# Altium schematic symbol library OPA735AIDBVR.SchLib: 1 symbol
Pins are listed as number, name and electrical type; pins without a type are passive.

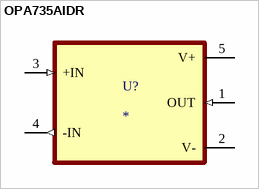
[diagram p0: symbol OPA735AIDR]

## OPA735AIDR
designator U?
MP: OPA735AIDR
footprint OPA735AIDBVR
pins: 1 OUT (in), 2 V- (power), 3 +IN (in), 4 -IN (out), 5 V+ (power)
